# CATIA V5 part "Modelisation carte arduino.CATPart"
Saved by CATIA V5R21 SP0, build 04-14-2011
Part number: Modélisation Carte Arduino
Bounding box of the stored display mesh (mm): x 0 to 106.6, y 0 to 53.3, z 0 to 13
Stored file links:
  C:\Users\2027.DESARCY-LEMIE30\Desktop\V15(20.03.2023)\Modelisation carte arduino.CATPart
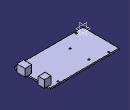
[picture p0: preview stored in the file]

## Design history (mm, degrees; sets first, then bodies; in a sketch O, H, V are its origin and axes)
Body1 (main body)
  Sketch1 on xy-plane, origin (0, 0, 0), H (1, 0, 0), V (0, 1, 0)
    line L1 (0, 53.3) -> (101.6, 53.3)
    line L2 (101.6, 53.3) -> (101.6, 0)
    line L3 (101.6, 0) -> (0, 0)
    line L4 (0, 0) -> (0, 53.3)
    point P4 (0, 0)
    length L3 = 101.6
    length L2 = 53.3
    horizontal: L1 H, L3 H
    vertical: L2 V, L4 V
    coincidence: P4 O
  Pad1: profile Sketch1, direction (0, 0, 1), length 2
  Sketch2 on face of Pad1 from Sketch1.L2, origin (101.6, 0, 0), H (0, 1, 0), V (0, 0, 1)
    line L1 (8.8, 13) -> (20.8, 13)
    line L2 (20.8, 13) -> (20.8, 2)
    line L3 (20.8, 2) -> (8.8, 2)
    line L4 (8.8, 2) -> (8.8, 13)
    reference projected line E1 (0, 2) -> (53.3, 2) from edge [face of Pad1 from Sketch1.L2 | end face of Pad1]
    line L5 (40.5, 13) -> (49.5, 13)
    line L6 (49.5, 13) -> (49.5, 2)
    line L7 (49.5, 2) -> (40.5, 2)
    line L8 (40.5, 2) -> (40.5, 13)
    reference projected line E2 (0, 2) -> (53.3, 2) from edge [face of Pad1 from Sketch1.L2 | end face of Pad1]
    distance L4 V = 8.8
    length L1 = 12
    length L2 = 11
    distance L2 L8 = 19.7
    length L5 = 9
    length L8 = 11
    horizontal: L1 H, L3 H, L5 H, L7 H
    vertical: L2 V, L4 V, L6 V, L8 V
    coincidence: L3 E1, E2 L7
  Pad2: profile Sketch2, direction (1, 0, 0), length 5, opposite side length 5
  Sketch3 on xy-plane, origin (0, 0, 0), H (1, 0, 0), V (0, 1, 0)
    circle A1 centre (87.6, 2.5) radius 1.3
    point P1 (87.6, 2.5)
    circle A2 centre (12.7, 2.5) radius 1.3
    point P2 (12.7, 2.5)
    circle A3 centre (87.6, 50.7) radius 1.3
    point P3 (87.6, 50.7)
    circle A4 centre (12.7, 50.7) radius 1.3
    point P4 (12.7, 50.7)
    reference projected line E1 (101.6, 0) -> (101.6, 53.3) from edge [face of Pad1 from Sketch1.L2 | end face of Pad1]
    circle A5 centre (36.8, 17.7) radius 1.3
    point P5 (36.8, 17.7)
    circle A6 centre (36.8, 45.6) radius 1.3
    point P6 (36.8, 45.6)
    reference projected line E2 (0, 0) -> (101.6, 0) from edge [face of Pad1 from Sketch1.L3 | end face of Pad1]
    construction line L1 (104.2729, 2.5) -> (-3.8985, 2.5)
    construction line L2 (36.8, 7.0859) -> (36.8, 48.7575)
    construction line L3 (110.6573, 50.7) -> (14.6616, 50.7)
    construction line L4 (87.6, -3.0536) -> (87.6, 62.1687)
    axis line L5 (12.7, -7.199) -> (12.7, 65.513)
    radius A4 = 1.3
    radius A3 = 1.3
    radius A1 = 1.3
    radius A2 = 1.3
    distance P1 E1 = 14
    radius A5 = 1.3
    radius A6 = 1.3
    distance P5 P2 V = 15.2
    distance P2 E2 = 2.5
    distance P5 P2 H = 24.1
    distance P2 P1 H = 74.9
    distance P5 P6 = 27.9
    distance P6 P4 V = 5.1
    horizontal: L1 H, L3 H
    coincidence: P2 L1, P1 L1, L2 P5, P6 L2, P4 L3, P3 L3, P3 L4, L4 P1, P4 L5, L5 P2
    vertical: L2 V, L4 V, L5 V
  Pocket1: profile Sketch3, direction (0, 0, -1), through (limit type 3)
